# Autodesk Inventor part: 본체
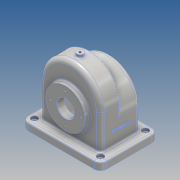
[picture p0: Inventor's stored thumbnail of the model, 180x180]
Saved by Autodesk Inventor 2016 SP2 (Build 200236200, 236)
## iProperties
Created: 2017-11
Part Number: 본체
Material: 알루미늄 6061
Document SubType Name: Modeling
Designer: Administrator
Density: 2.7 g/cm^3
Appearance: 알루미늄 - 평지
Author: Administrator
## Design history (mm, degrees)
sketch "스케치1"
  geometry: L1 (-63, 55)-(63, 55); L2 (75, 43)-(75, -43); L3 (63, -55)-(-63, -55); L4 (-75, -43)-(-75, 43); L5 (-75, 55)-(75, -55); L6 (75, 55)-(-75, -55); A1 r 12 centre (-63, 43) between (-63, 55) and (-75, 43); A2 r 12 centre (-63, -43) between (-75, -43) and (-63, -55); A3 r 12 centre (63, -43) between (63, -55) and (75, -43); A4 r 12 centre (63, 43) between (75, 43) and (63, 55); 1 further point
  constraints: 12 end point, 8 point on circle, 8 point on line, 8 tangent, 4 centre point, 3 equal radius, 2 midpoint, 2 parallel, 1 horizontal, 1 perpendicular
  dimensions: "d0" = 150 distance of L5.end L6.end; "d1" = 110 distance of L6.start L5.end; "d2" = 12 radius of A1
extrude "돌출1" new body sketch "스케치1" distance "d3" = 15; taper "d4" = 0 deg
sketch "스케치2"
  geometry: L1 (-63, 0)-(63, 0) reference; L2 (-58, 80)-(-58, 15); L3 (58, 80)-(58, 15); L4 (-63, 15)-(63, 15) reference; A1 r 58 centre (0, 80) between (58, 80) and (-58, 80); 2 further points
  constraints: 4 end point, 2 point on circle, 2 point on line, 2 tangent, 1 centre point, 1 midpoint, 1 perpendicular, 1 vertical, 1 vertical alignment
  dimensions: "d5" = 116 diameter of A1; "d6" = 80 distance from line of A1.centre L1
extrude "돌출2" join sketch "스케치2" distance "d7" = 38; taper "d8" = 0 deg
sketch "스케치3"
  geometry: L1 (-63, 0)-(63, 0) reference; L2 (-58, -15)-(-58, -57); L3 (-58, -80)-(-58, -15) reference; L4 (58, -15)-(58, -57); L5 (58, -15)-(-58, -15) reference; A1 r 58 centre (0, -80) between (-58, -80) and (58, -80) reference; A2 r 58 centre (0, -57) between (-58, -57) and (58, -57); 1 further point
  constraints: 4 end point, 2 point on circle, 2 point on line, 2 tangent, 1 centre point, 1 collinear, 1 vertical, 1 vertical alignment
  dimensions: "d9" = 116 diameter of A2; "d10" = 57 distance from line of A2.centre L1
extrude "돌출3" join sketch "스케치3" distance "d11" = 38; taper "d12" = 0 deg
sketch "스케치5"
  geometry: L1 (-63, -55)-(63, -55) reference; L2 (-41.963, -38)-(49.261, -38); C1 r 6 at (0, -19); 1 further point
  constraints: 2 end point, 1 centre point, 1 horizontal, 1 vertical alignment
  dimensions: "d14" = 12 diameter of C1; "d15" = 38 distance from line of L2 point (0, 0); "d16" = 19 distance from line of C1.centre L2
extrude "돌출4" join sketch "스케치5" distance "d17" = 144; taper "d18" = 0 deg
sketch "스케치7"
  geometry: L1 (-63, 0)-(63, 0) reference; C1 r 37.5 at (0, 65); 2 further points
  constraints: 1 centre point, 1 midpoint, 1 vertical alignment
  dimensions: "d20" = 75 diameter of C1; "d21" = 65 distance from line of C1.centre L1
extrude "돌출5" join sketch "스케치7" distance "d22" = 9; taper "d23" = 0 deg
sketch "스케치8"
  geometry: L1 (63, 0)-(-63, 0) reference; C1 r 31 at (0, -65); 2 further points
  constraints: 1 centre point, 1 midpoint, 1 vertical alignment
  dimensions: "d24" = 62 diameter of C1; "d25" = 65 distance from line of C1.centre L1
extrude "돌출6" join sketch "스케치8" distance "d26" = 10; taper "d27" = 0 deg
sketch "스케치9"
  geometry: C1 r 31 at (0, 0) reference; C2 r 16 at (0, 0); 1 further point
  constraints: 1 centre point, 1 coincident
  dimensions: "d28" = 32 diameter of C2
extrude "돌출7" cut sketch "스케치9" stored distance "d29" = 10; taper "d30" = 0 deg
node "작업 평면1"
sketch "스케치11"
  geometry: L1 (-63, 0)-(63, 0) reference; L2 (53, 0)-(53, 80); L3 (-53, 0)-(-53, 80); A1 r 53 centre (0, 80) between (53, 80) and (-53, 80); 2 further points
  constraints: 4 end point, 2 point on circle, 2 point on line, 2 tangent, 2 vertical, 1 centre point, 1 midpoint, 1 vertical alignment
  dimensions: "d34" = 106 diameter of A1; "d35" = 80 distance from line of A1.centre L1
extrude "돌출8" cut sketch "스케치11" distance "d36" = 28; taper "d37" = 0 deg
node "작업 평면2"
sketch "스케치12"
  geometry: L1 (-63, 0)-(63, 0) reference; L2 (53, 0)-(53, 57); L3 (-53, 0)-(-53, 57); A1 r 53 centre (0, 57) between (53, 57) and (-53, 57); 2 further points
  constraints: 4 end point, 2 point on circle, 2 point on line, 2 tangent, 2 vertical, 1 centre point, 1 midpoint, 1 vertical alignment
  dimensions: "d39" = 106 diameter of A1; "d40" = 57 distance from line of A1.centre L1
extrude "돌출9" cut sketch "스케치12" distance "d41" = 38; taper "d42" = 0 deg
sketch "스케치13"
  geometry: C1 r 16 at (0, 0) reference; 5 further points
  constraints: 2 horizontal alignment, 2 vertical alignment
  dimensions: "d43" = 58 distance of point (-29, 0) point (29, 0); "d44" = 58 distance of point (0, -29) point (0, 29); "d45" = 29 distance of point (0, -29) C1.centre; "d46" = 29 distance of C1.centre point (29, 0)
hole "구멍1" sketch "스케치13" at (0, 29), (29, 0), (0, -29), (-29, 0) diameter "d47" = 2.459; stored, may be unused: countersink angle "d51" = 90 deg, drill point angle "d53" = 0 deg; dims "d48" = 5, "d49" = 4, "d50" = 2, "d52" = 8
sketch "스케치14"
  geometry: C1 r 16 at (0, 0) reference; 5 further points
  constraints: 2 horizontal alignment, 2 vertical alignment
  dimensions: "d54" = 52 distance of point (26, 0) point (-26, 0); "d55" = 52 distance of point (0, 26) point (0, -26); "d56" = 26 distance of C1.centre point (-26, 0); "d57" = 26 distance of point (0, 26) C1.centre
hole "구멍2" sketch "스케치14" at (0, -26), (-26, 0), (0, 26), (26, 0) diameter "d58" = 2.459; stored, may be unused: countersink angle "d62" = 90 deg, drill point angle "d64" = 0 deg; dims "d59" = 5, "d60" = 4, "d61" = 2, "d63" = 8
sketch "스케치15"
  geometry: A1 r 12 centre (-63, -43) between (-75, -43) and (-63, -55) reference; A2 r 12 centre (63, 43) between (75, 43) and (63, 55) reference; A3 r 12 centre (-63, 43) between (-63, 55) and (-75, 43) reference; A4 r 12 centre (63, -43) between (63, -55) and (75, -43) reference; 5 further points
  constraints: 4 coincident
hole "구멍3" sketch "스케치15" at (-63, 43), (63, 43), (63, -43), (-63, -43) diameter "d65" = 5; stored, may be unused: countersink angle "d69" = 90 deg, drill point angle "d71" = 0 deg; dims "d66" = 5, "d67" = 12, "d68" = 5, "d70" = 8
sketch "스케치16"
  geometry: C1 r 6 at (0, 0) reference; 2 further points
  constraints: 1 coincident
hole "구멍4" sketch "스케치16" at (0, 0) diameter "d72" = 4.459; stored, may be unused: countersink angle "d76" = 90 deg, drill point angle "d78" = 0 deg; dims "d73" = 10, "d74" = 12, "d75" = 5, "d77" = 50
node "작업 평면3"
sketch "스케치17"
  geometry: L1 (-43, 0)-(43, 0) reference; L2 (-38, 15)-(-38, 80) reference; 2 further points
  constraints: 1 other
  dimensions: "d80" = 40 distance from line of point (0, 40) L1; "d81" = 38 distance from line of point (0, 40) L2
feature "엠보싱1" sketch "스케치17" dims "d0" = 150, "d1" = 110, "d2" = 12, "d5" = 116, "d6" = 80, "d82" = 0.5, "d83" = 0
fillet "모깎기1" dims "d84" = 8, "d85" = 3
fillet "모깎기2" dims "d86" = 3
chamfer "모따기1" distance "d87" = 1; stored, may be unused: second distance "d88" = 2, angle "d89" = 45 deg
node "솔리드1"
other parameters: "d33" = -5, "d38" = -5, "d79" = 75
